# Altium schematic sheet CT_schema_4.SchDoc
size 373 x 245 mm
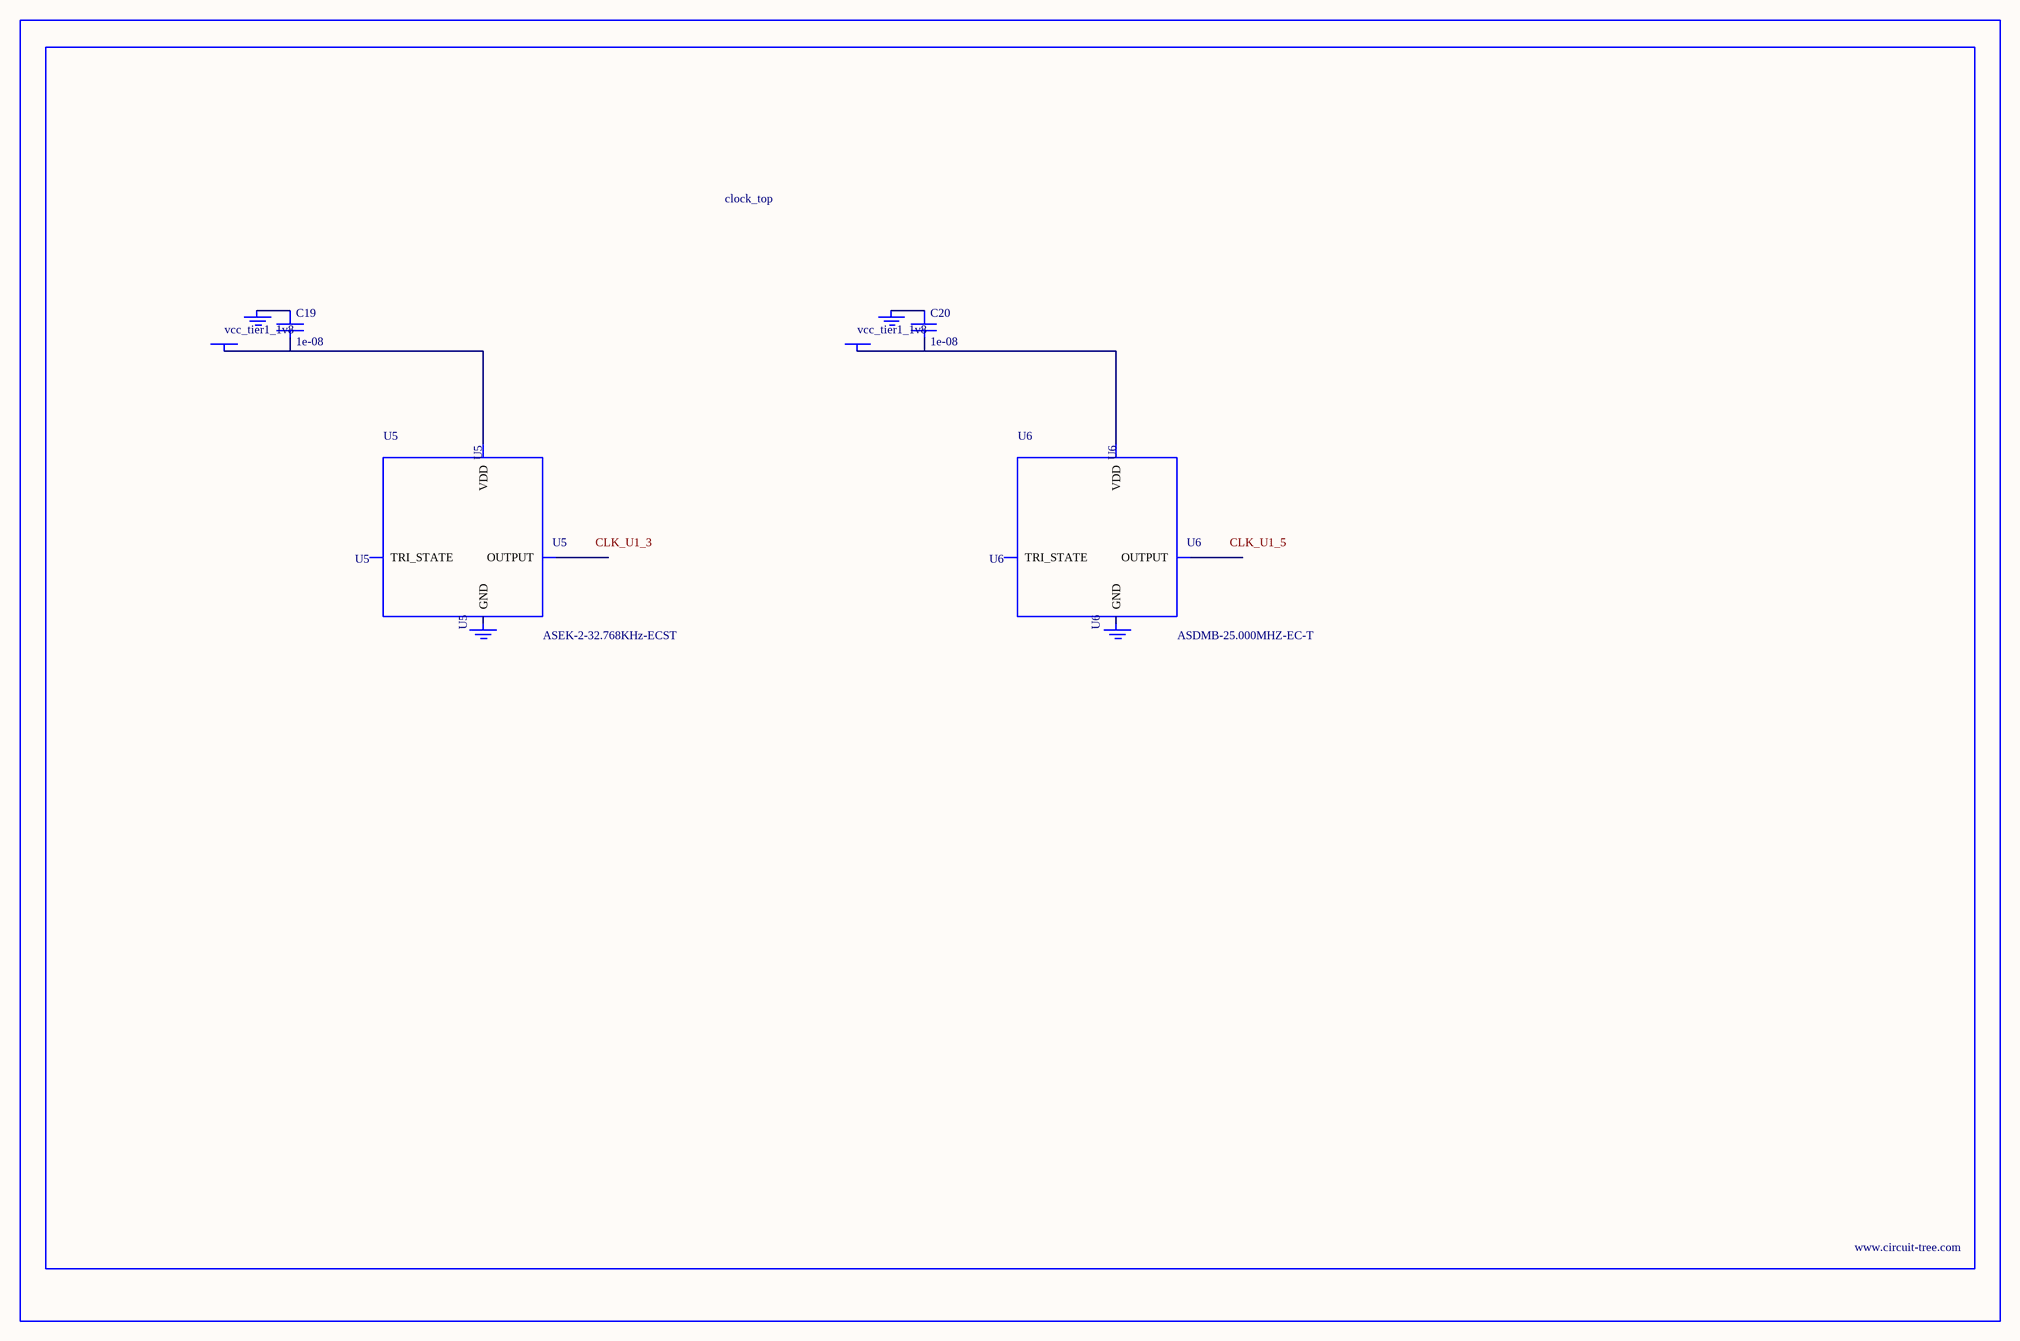
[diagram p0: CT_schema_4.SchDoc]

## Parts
BORDER3  (no value)
C19  1e-08  [C0402]
C20  1e-08  [C0402]
GND_INSTANCE_3_0  (no value)
GND_INSTANCE_3_1  (no value)
GND_INSTANCE_3_2  (no value)
GND_INSTANCE_3_3  (no value)
POWER_INSTANCE_3_0  vcc_tier1_1v8
POWER_INSTANCE_3_1  vcc_tier1_1v8
U5  ASEK-2-32.768KHz-ECST  [ASEK]
U6  ASDMB-25.000MHZ-EC-T  [ASDMB-XX.XXXXMHZ-XX-XX-XXX]

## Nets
NetC19_1: C19.1 GND_INSTANCE_3_0.0(GND)
NetC19_2: C19.2 POWER_INSTANCE_3_0.0(PWR) U5.4(VDD)
NetC20_1: C20.1 GND_INSTANCE_3_2.0(GND)
NetC20_2: C20.2 POWER_INSTANCE_3_1.0(PWR) U6.4(VDD)

Not connected (* = marked no-connect by the designer): GND_INSTANCE_3_1 0(GND); GND_INSTANCE_3_3 0(GND); U5 1(TRI_STATE) 2(GND) 3(OUTPUT); U6 1(TRI_STATE) 2(GND) 3(OUTPUT)

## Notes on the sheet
- Labels drawn without touching a wire or pin: CLK_U1_3, CLK_U1_5

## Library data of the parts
BORDER3 = BORDER_PAGE3
C19 C20 = C0402C103K3RAC
GND_INSTANCE_3_0-GND_INSTANCE_3_3 = GND
POWER_INSTANCE_3_0 POWER_INSTANCE_3_1 = PWR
